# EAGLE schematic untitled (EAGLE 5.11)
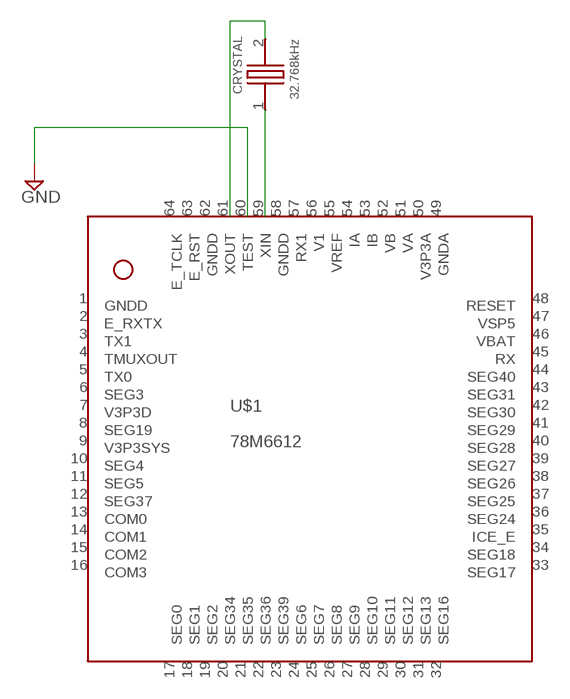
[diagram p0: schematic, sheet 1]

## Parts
CRYSTAL  32.768kHz  CRYSTAL-SMD-5.5X2.2C  [CRYSTAL-SMD-5.5X2.2]
U$1  78M6612  [QFP-64]

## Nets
GND: U$1.60(TEST)
N$1: CRYSTAL.1 U$1.59(XIN)
N$2: CRYSTAL.2 U$1.61(XOUT)
Unconnected: U$1.1(GNDD) U$1.2(E_RXTX) U$1.3(TX1) U$1.4(TMUXOUT) U$1.5(TX0) U$1.6(SEG3) U$1.7(V3P3D) U$1.8(SEG19) U$1.9(V3P3SYS) U$1.10(SEG4) U$1.11(SEG5) U$1.12(SEG37) U$1.13(COM0) U$1.14(COM1) U$1.15(COM2) U$1.16(COM3) U$1.17(SEG0) U$1.18(SEG1) U$1.19(SEG2) U$1.20(SEG34) U$1.21(SEG35) U$1.22(SEG36) U$1.23(SEG39) U$1.24(SEG6) U$1.25(SEG7) U$1.26(SEG8) U$1.27(SEG9) U$1.28(SEG10) U$1.29(SEG11) U$1.30(SEG12) U$1.31(SEG13) U$1.32(SEG16) U$1.33(SEG17) U$1.34(SEG18) U$1.35(ICE_E) U$1.36(SEG24) U$1.37(SEG25) U$1.38(SEG26) U$1.39(SEG27) U$1.40(SEG28) U$1.41(SEG29) U$1.42(SEG30) U$1.43(SEG31) U$1.44(SEG40) U$1.45(RX) U$1.46(VBAT) U$1.47(VSP5) U$1.48(RESET) U$1.49(GNDA) U$1.50(V3P3A) U$1.51(VA) U$1.52(VB) U$1.53(IB) U$1.54(IA) U$1.55(VREF) U$1.56(V1) U$1.57(RX1) U$1.58(GNDD) U$1.62(GNDD) U$1.63(E_RST) U$1.64(E_TCLK)

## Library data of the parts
CRYSTAL = trl:CRYSTAL-SMD-5.5X2.2
U$1 = trl:78M6612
